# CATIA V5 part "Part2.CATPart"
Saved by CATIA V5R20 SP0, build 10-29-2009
Part number: Part2
Bounding box of the stored display mesh (mm): x -75 to 90, y -15 to 15, z 0 to 30
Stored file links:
  E:\Ehsan\Amoozesh\CATIA\CATIA Course\Advanced\Exercises\DMU Kinematic\12\Part2.CATPart
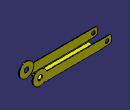
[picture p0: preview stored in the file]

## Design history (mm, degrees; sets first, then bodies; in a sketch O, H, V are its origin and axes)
Body1 (main body)
  Sketch1 on zx-plane, origin (0, 0, 0), H (-1, 0, 0), V (0, 0, 1)
    line L1 (-75, 0) -> (75, 0)
    length L1 = 150
    midpoint: L1 O
    horizontal: L1 H
  Pad1: profile Sketch1, direction (0, 1, 0), length 15, thin wall 20
  Fillet1: radius 2, on edge [face of Pad1 | end face of Pad1]
  Shell1: IntOffset 1, Face (face of Pad1; start face of Pad1; face of Pad1; face of Pad1), ExtOffset 0
  Sketch2 on zx-plane, origin (0, 0, 0), H (-1, 0, 0), V (0, 0, 1)
    point P1 (-65, 3)
    line L1 (-65, 3) -> (-87.7548, 3)
    line L2 (-87.7548, 3) -> (-87.7548, -4.5707)
    line L3 (-87.7548, -4.5707) -> (-65, -4.5707)
    line L4 (-65, -4.5707) -> (-65, 3)
    reference projected line E1 (-75, 20) -> (-75, 0) from edge [face of Pad1 | end face of Pad1]
    distance P1 H = 3
    distance L4 E1 = 10
    horizontal: L1 H, L3 H
    vertical: L2 V, L4 V
  Pocket1: profile Sketch2, direction (0, 1, 0), length 31
  Sketch3 on end face of Pad1, origin (0, 15, 0), H (-1, 0, 0), V (0, 0, 1)
    circle A1 centre (-75, 15) radius 15
    point P1 (-75, 15)
    distance P1 H = 15
    distance P1 V = 75
    radius A1 = 15
  Pad2: profile Sketch3, direction (0, -1, 0), length 1.5
  Sketch4 on face of Pad2, origin (0, 15, 0), H (-1, 0, 0), V (0, 0, 1)
    circle A1 centre (-75, 15) radius 5
    reference projected circle E1 centre (-75, 15) radius 15 from edge [face of Pad2 from Sketch3.A1 | face of Pad2]
    circle A2 centre (65.9, 11) radius 4
    point P2 (65.9, 11)
    reference projected line E2 (75, 0) -> (75, 20) from edge [face of Pad1 | face of Pad2]
    radius A1 = 5
    distance P2 H = 11
    radius A2 = 4
    distance P2 E2 = 9.1
    concentricity: A1 E1
  Pocket2: profile Sketch4, direction (0, -1, 0), length 1.5
  Sketch5 on face of Pad2, origin (0, 15, 0), H (-1, 0, 0), V (0, 0, 1)
    point P1 (55, 3)
    line L1 (55, 3) -> (91.1942, 3)
    line L2 (91.1942, 3) -> (91.1942, -6.0968)
    line L3 (91.1942, -6.0968) -> (55, -6.0968)
    line L4 (55, -6.0968) -> (55, 3)
    reference projected line E1 (75, 0) -> (75, 20) from edge [face of Pad1 | face of Pad2]
    distance P1 H = 3
    distance L4 E1 = 20
    horizontal: L1 H, L3 H
    vertical: L2 V, L4 V
  Pocket3: profile Sketch5, direction (0, -1, 0), length 31
  Mirror1: of the body so far, about zx-plane
  Fillet2: radius 5, on edge [face of Pocket3 from Sketch5.L1 | face of Pad1]; edge [face of Mirror1 | face of Mirror1] (x2); edge [face of Pad1 | face of Pad1]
